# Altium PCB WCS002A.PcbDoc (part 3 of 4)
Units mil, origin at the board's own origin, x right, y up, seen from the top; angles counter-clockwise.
Board outline 2300 x 4058 mil, 4 copper layers (TOP, GND, PWR, BOTTOM), stack 28.8 mil thick; 311 components, 217 nets, 982 pads, 644 vias.
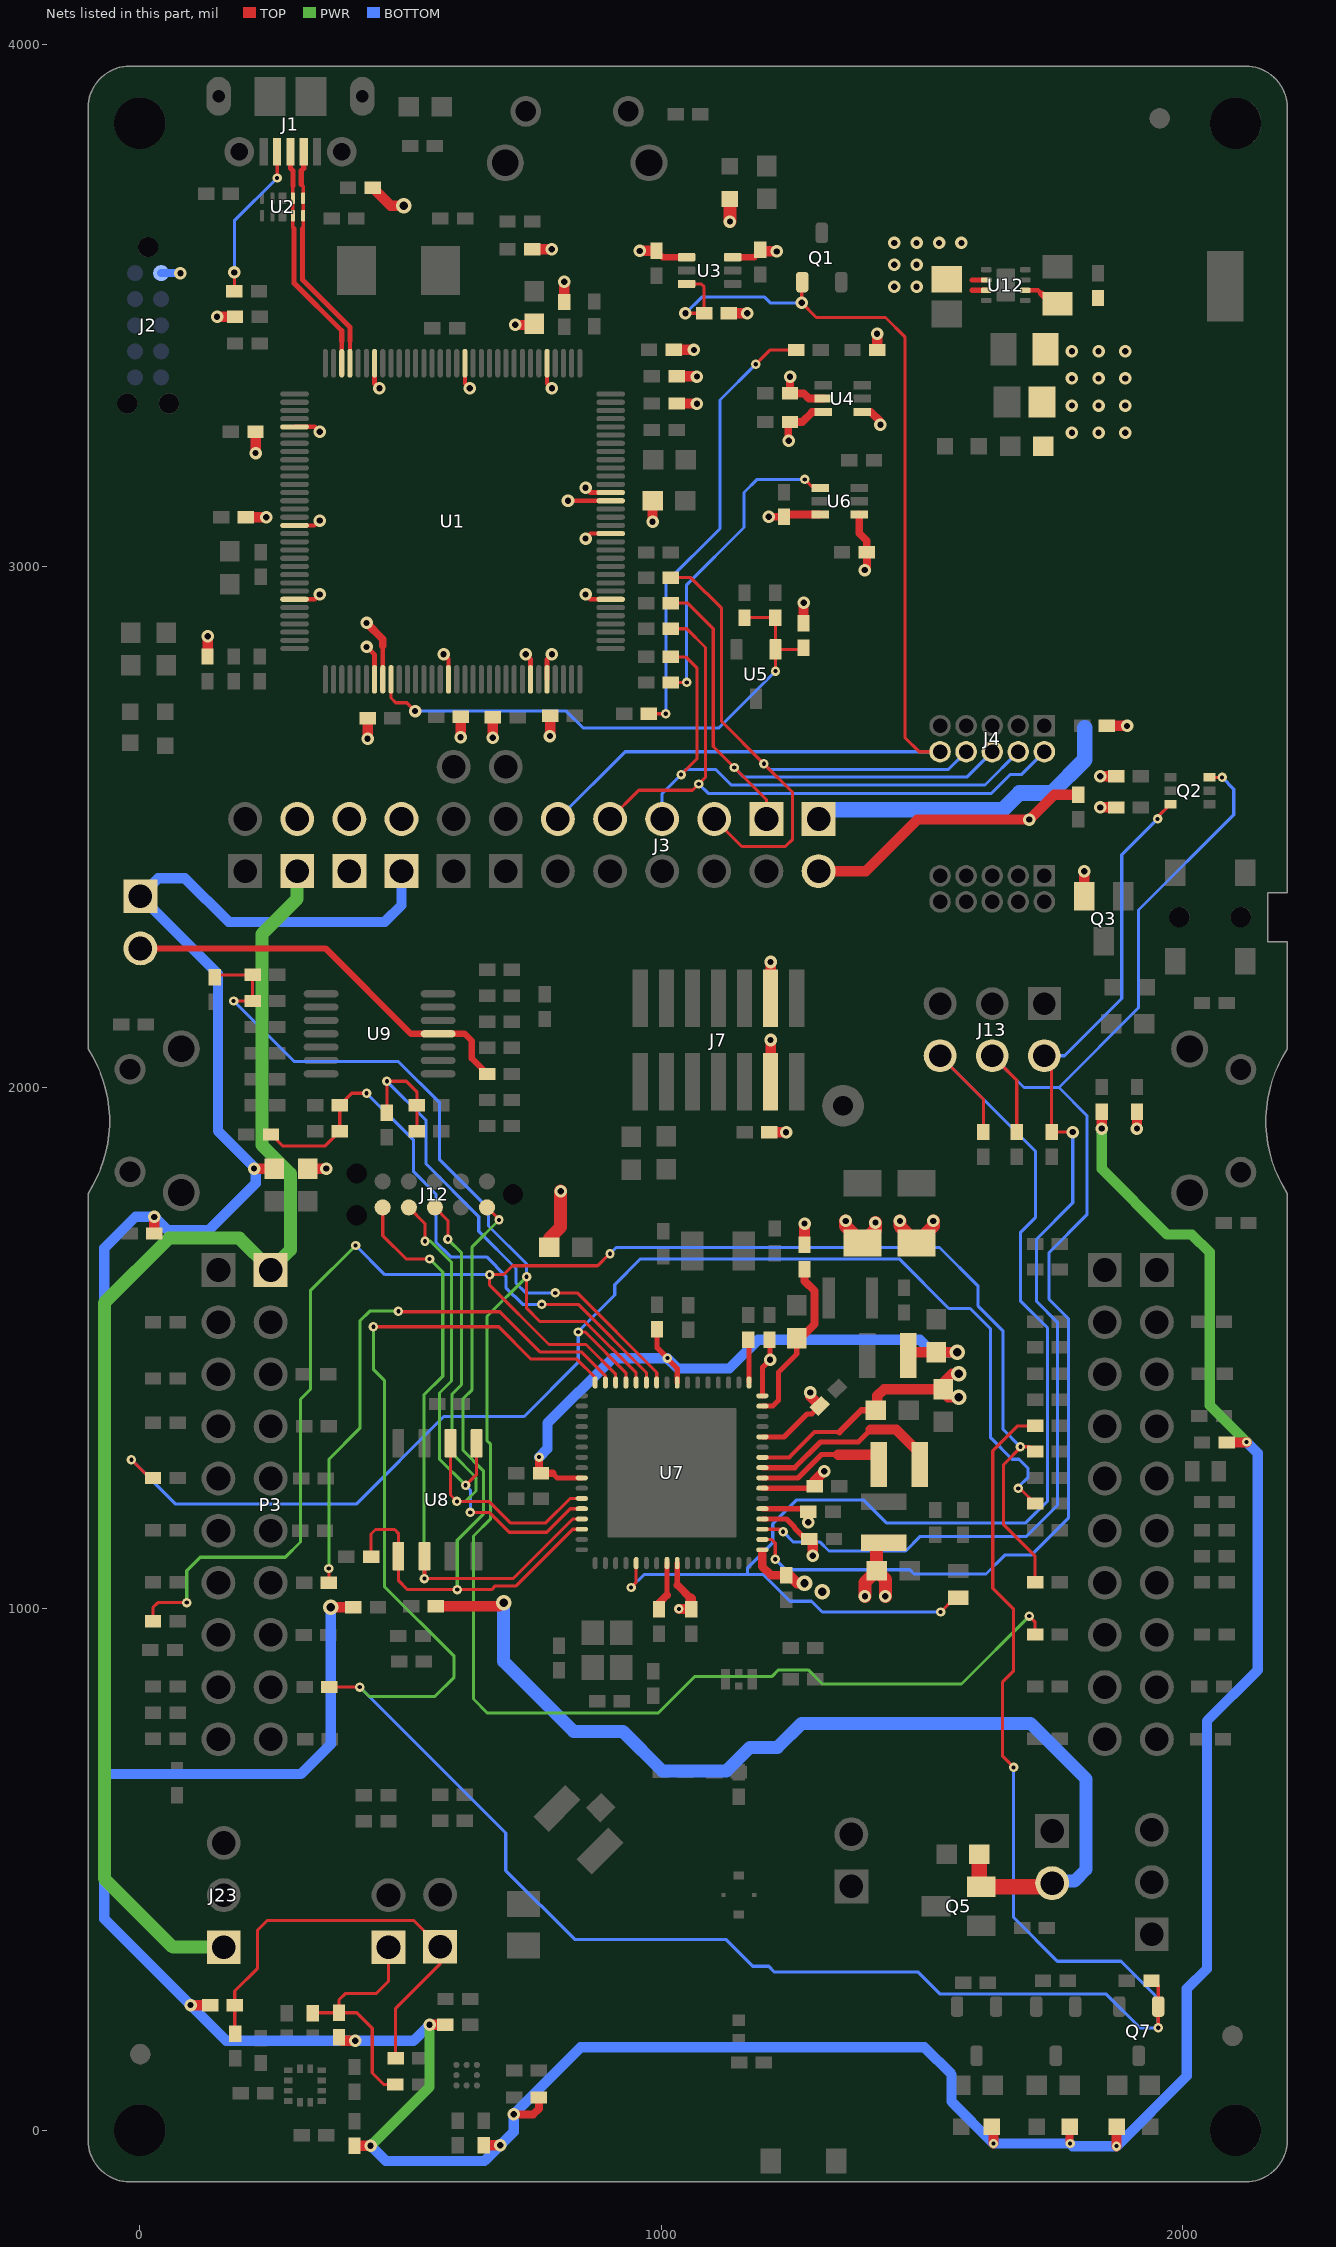
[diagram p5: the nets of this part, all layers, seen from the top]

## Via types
v1: diameter 18, hole 8, TOP to BOTTOM, tented both sides, 344 vias
v2: diameter 24, hole 12, TOP to BOTTOM, tented both sides, 244 vias
v3: diameter 24, hole 12.1, TOP to BOTTOM, 36 vias
v4: diameter 30, hole 16, TOP to BOTTOM, tented both sides, 18 vias
v5: diameter 24, hole 12.1, TOP to BOTTOM, tented top, 2 vias

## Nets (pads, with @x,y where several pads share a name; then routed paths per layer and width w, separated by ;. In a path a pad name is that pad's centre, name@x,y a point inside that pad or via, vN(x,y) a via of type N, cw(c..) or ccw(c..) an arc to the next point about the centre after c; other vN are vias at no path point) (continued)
P58_GPIO_03: C55.1 R108.2 R110.2 U7.58 | length 1051.6
  TOP w6: R108.2@473.79,1951.41 v1(473.79,2011.79) 510.79,2011.79 531.17,1991.41 R110.2@531.17,1965.79 C55.1@531.17,1915.79 ; v1(796.79,1605.79) 838.7,1605.79 991.26,1453.23 U7.58@991.26,1434.02
  BOTTOM w6: v1(473.79,2011.79) 549,1936.57 549,1853 650,1752 650,1724 721.5,1652.5 721.5,1624.5 740.21,1605.79 v1(796.79,1605.79)
P59_GPIO_04: C56.1 R109.2 R111.2 U7.59 | length 1143.9
  TOP w6: R109.2@251.41,1909.79 273.41,1887.79 355.79,1887.79 383.41,1915.41 C56.1@383.41,1915.79 R111.2@383.41,1965.79 406.41,1988.79 v1(434.79,1988.79) ; v1(770.79,1583.79) 840.91,1583.79 971.58,1453.12 U7.59@971.57,1434.02
  BOTTOM w6: v1(434.79,1988.79) 525,1898.57 525,1838 568,1795 568,1703 596,1675 665,1675 702,1638 702,1616 734.21,1583.79 v1(770.79,1583.79)
P60_GPIO_05: C53.1 R77.1 R100.2 R102.2 U7.60 | length 3455.1
  TOP w6: R100.2@143.79,2211.41 148.17,2215.79 C53.1@216.17,2215.79 R102.2@216.17,2165.79 v1(179.79,2165.79) ; v1(741.79,1636.79) 741.79,1575.79 742.15,1576.15 767.5,1550.79 853.79,1550.79 951.87,1452.7 U7.60@951.89,1434.02 ; v1(1705.79,985.79) 1717.17,974.41 R77.1@1717.17,950.79
  PWR w6: v1(741.79,1636.79) 665.79,1560.79 665.79,1322.21 672.79,1315.21 672.79,1172.59 639.79,1139.59 639.79,826.79 666.79,799.79 993.79,799.79 1063.79,869.79 1211.79,869.79 1224.79,882.79 1281.79,882.79 1308.79,855.79 1575.79,855.79 v1(1705.79,985.79)
  BOTTOM w6: v1(179.79,2165.79) 295.79,2049.79 495.79,2049.79 575,1970.57 575,1861 669,1767 669,1754.28 668.79,1754.07 668.79,1734.21 741.79,1661.21 v1(741.79,1636.79)
P61_GPIO_06: R75.1 R98.1 U7.61 | length 2575.1
  TOP w6: v1(-16.21,1285.79) 18.79,1250.79 R75.1@25.17,1250.79 ; v1(840.79,1530.79) 853.99,1530.79 932.21,1452.57 U7.61@932.2,1434.02 ; v1(1684.79,1230.79) 1688.17,1230.79 R98.1@1717.17,1201.79
  BOTTOM w6: v1(-16.21,1285.79) 68.79,1200.79 414.79,1200.79 582.79,1368.79 737.07,1368.79 840.79,1472.5 v1(840.79,1530.79) 840.79,1531.79 910.79,1601.79 910.79,1621.79 960.1,1671.1 1456.4,1671.1 1551.71,1575.79 1592.56,1575.79 1631.79,1536.56 1631.79,1327.79 1672.79,1286.79 1686.07,1286.79 1703.79,1269.07 1703.79,1252.5 1684.79,1233.5 v1(1684.79,1230.79) v1@1685.79,1230.79
P62_GPIO_07: R73.1 R87.1 R94.1 U7.62 | length 3298.6
  TOP w6: R87.1@25.17,975.79 25.17,1002.57 34.39,1011.79 v1(89.79,1011.79) ; v1(901.79,1680.79) 900.79,1680.79 878,1658 714.72,1658 697.5,1640.79 v1(670.79,1640.79) 670.79,1620.79 784.79,1506.79 855.79,1506.79 912.49,1450.08 U7.62@912.52,1434.02 ; R73.1@1717.17,1050.79 1717.17,1100.41 1656.79,1160.79 1656.79,1276.79 1690.79,1310.79 1708.17,1310.79 R94.1@1717.17,1301.79
  PWR w6: v1(89.79,1011.79) 89.79,1072.99 115.59,1098.79 278.79,1098.79 308.1,1128.1 308.1,1401.7 327,1420.6 327,1610 v1(413.79,1696.79)
  BOTTOM w6: v1(413.79,1696.79) 469.79,1640.79 v1(670.79,1640.79) ; v1(901.79,1680.79) 913.79,1692.79 1533.79,1692.79 1607.79,1618.79 1607.79,1580.36 1655.79,1532.36 1655.79,1343.79 v1(1688.79,1310.79)
P63_GPIO_08: R84.2 U7.63 | length 1068.2
  TOP w6: R84.2@362.41,1049.79 v1(362.41,1077.17) ; v1@496.79,1569.79 690.21,1569.79 767.21,1492.79 846.79,1492.79 892.84,1446.74 U7.63@892.83,1434.02
  PWR w6: v1(362.41,1077.17) 362.41,1286.41 422,1346 422,1552 440.79,1570.79 v1(495.79,1570.79)
P64_GPIO_09: Q7.1 R63.1 R90.2 R153.1 U7.64 | length 4846.1
  TOP w6: R90.2@363.41,849.79 v1(421.79,849.79) ; v1(447.79,1540.79) 688.21,1540.79 750.21,1478.79 837.87,1478.79 873.11,1443.54 U7.64@873.11,1434.02 ; v1(1675.79,695.79) 1654.79,716.79 1654.79,859.79 1675.79,880.79 1675.79,999.21 1635.79,1039.21 1635.79,1302.79 1683.79,1350.79 R63.1@1717.17,1350.79 ; R153.1@1938.41,286.79 R153.1@1940.41,286.79 1944.11,286.79 1953.19,277.71 Q7.1@1953.19,237.03 v1(1953.19,196.19)
  PWR w6: v1(421.79,849.79) 439.79,831.79 565.79,831.79 602.79,868.79 602.79,908.79 469,1042.57 469,1438 447.79,1459.21 v1(447.79,1540.79)
  BOTTOM w6: v1(421.79,849.79) 701.79,569.79 701.79,497.79 833.79,365.79 1123.91,365.79 1175.5,314.2 1206.2,314.2 1217.3,303.1 1492.9,303.1 1535.21,260.79 1853.79,260.79 1918.39,196.19 v1(1953.19,196.19) 1953.19,252.41 1881.81,323.79 1759.81,323.79 1675.79,407.81 v1(1675.79,695.79)
PA_SWN: L5.1 U7.41 | length 372.9
  TOP w10: U7.41@1194.02,1270.63 1256.08,1270.63 1305.24,1319.79 1377.78,1319.79 1401.78,1343.79
  TOP w20: 1401.78,1343.79 1450.79,1343.79 1496.16,1298.42 L5.1@1496.16,1276.79
PA_SWP: L5.2 U7.40 | length 261
  TOP w10: U7.40@1194.02,1250.94 1262.38,1250.95 1307.22,1295.79 1339.59,1295.79
  TOP w20: 1339.59,1295.79 1417.42,1295.79 L5.2@1417.42,1276.79
SENS_I2C_SCL: J15.1 R119.2 R133.1 R134.1 | length 466
  TOP w6: R133.1@331.79,224.03 332.79,225.03 R119.2@381.79,225.03 ; J15.1@476.79,350.79 476.79,285.6 452.97,261.79 393.79,261.79 381.79,249.79 R119.2@381.79,225.03 ; R134.1@490.17,87.41 467.79,87.41 445.79,109.41 445.79,195.46 416.22,225.03 R119.2@381.79,225.03
SENS_I2C_SDA: J16.1 R118.2 R130.1 R135.1 | length 845
  TOP w6: R130.1@182.79,185.03 181.89,185.93 R118.2@181.89,239.79 181.89,266.89 225.79,310.79 225.79,383.79 243.79,401.79 525.79,401.79 J16.1@575.79,351.79 575.79,318.79 490.42,233.42 R135.1@490.42,137.62
SFL_CLK: J12.8 U7.11 U8.6 | length 1019
  TOP w6: J12.8@565.79,1769.79 590.79,1744.79 v1(590.79,1708.79) ; U8.6@595.79,1307.28 595.79,1218.19 v1(608.03,1205.94) 669.46,1205.94 710.61,1164.79 778.79,1164.79 825.58,1211.58 U7.11@847.56,1211.57
  PWR w6: v1(590.79,1708.79) 616.79,1682.79 616.79,1429.79 598.79,1411.79 598.79,1297.79 644.79,1251.79 644.79,1225.79 624.94,1205.94 v1(608.03,1205.94)
SFL_CS: J12.10 R41.2 U7.14 U8.1 | length 1407.8
  TOP w6: R41.2@443.41,1099.79 443.41,1143.41 451.9,1151.9 488.7,1151.9 495.79,1144.81 U8.1@495.79,1100.74 495.79,1054.41 513.41,1036.79 v1(608.79,1036.79) 674.59,1036.79 681.59,1043.79 721.59,1043.79 830.32,1152.52 U7.14@847.56,1152.52 ; J12.10@665.79,1769.79 688.79,1746.79 v1(688.79,1745.79)
  PWR w6: v1(608.79,1036.79) 608.79,1131.5 658.79,1181.5 658.79,1264.79 619.79,1303.79 619.79,1402.79 637.2,1420.2 637.2,1694.2 v1(688.79,1745.79)
SFL_DIN: J12.6 U7.13 U8.2 | length 1212
  TOP w6: J12.6@465.79,1769.79 465.79,1715.79 510.79,1670.79 v1(555.79,1670.79) ; v1(545.79,1057.79) 715.79,1057.79 830.21,1172.21 U7.13@847.56,1172.2
  TOP w8: v1(545.79,1057.79) U8.2@545.79,1100.74 U8.2@545.79,1119.72
  PWR w6: v1@544.79,1057.79 544.79,1409.99 580.79,1445.99 580.79,1645.79 v1(555.79,1670.79)
SFL_DOUT: J12.7 U7.12 U8.5 | length 991.2
  TOP w6: J12.7@515.79,1769.79 546.79,1738.79 v1(546.79,1704.79) ; v1(624.79,1236.79) 645.79,1257.79 U8.5@645.79,1311.85 ; v1(633.79,1184.79) 670.31,1184.79 708.31,1146.79 780.59,1146.79 825.69,1191.89 U7.12@847.56,1191.89
  PWR w6: v1(546.79,1704.79) 557.54,1704.79 597.79,1664.54 597.79,1436.79 574.79,1413.79 574.79,1286.79 v1(624.79,1236.79)
  BOTTOM w6: v1(624.79,1236.79) 633.79,1227.79 v1(633.79,1184.79)
SOP0: J13.2 Q2.3 R49.1 U7.35 | length 2179.2
  TOP w6: U7.35@1194.02,1152.52 1229.06,1152.52 v1(1233.79,1147.79) ; J13.2@1734.79,2060.79 1748.79,2046.79 R49.1@1748.79,1914.41 v2(1789.41,1914.41) ; v1(1952.09,2514.99) 1952.09,2518.8 Q2.3@1976.69,2543.4
  BOTTOM w6: v1(1233.79,1147.79) 1253.79,1127.79 1304.79,1127.79 1321.79,1110.79 1468.79,1110.79 1496.79,1138.79 1700.49,1138.79 1759.79,1198.09 1759.79,1549.79 1719.79,1589.79 1719.79,1708.79 1789.41,1778.41 v2(1789.41,1914.41) ; J13.2@1734.79,2060.79 1773.49,2060.79 1883.3,2170.6 1883.3,2446.2 v1(1952.09,2514.99)
SOP1: J13.4 Q2.6 R50.1 U7.34 | length 2656.6
  TOP w6: U7.34@1194.02,1132.83 1211.79,1132.84 1218.79,1125.84 v1(1218.79,1095.01) ; J13.4@1634.79,2060.79 1681.79,2013.79 R50.1@1681.79,1914.41 ; Q2.6@2051.49,2594.58 v1(2075.81,2594.58)
  BOTTOM w6: v1(1218.79,1095.01) 1239.01,1074.79 1476.79,1074.79 1484.79,1066.79 1622.79,1066.79 1658.79,1102.79 1709.79,1102.79 1780.79,1173.79 1780.79,1556.79 1743.79,1593.79 1743.79,1682.79 1816.4,1755.4 1816.4,1946.17 1762.79,1999.79 ; J13.4@1634.79,2060.79 1695.79,1999.79 1762.79,1999.79 ; v1(2075.81,2594.58) 2098.2,2572.19 2098.2,2522.9 1915.5,2340.2 1915.5,2152.5 1762.79,1999.79
SOP2: D4.2 J13.6 R51.1 U7.21 | length 2572.8
  TOP w6: v1(942.12,1040.79) 951.89,1050.56 U7.21@951.89,1087.56 ; J13.6@1534.79,2060.79 1617.79,1977.79 R51.1@1617.79,1914.41 ; v1(1535.79,993.79) 1563.2,1021.2 D4.2@1569.79,1021.2
  BOTTOM w6: v1(942.12,1040.79) 967.12,1065.79 1165.79,1065.79 ; J13.6@1534.79,2060.79 1717.6,1877.97 1717.6,1750.3 1688.79,1721.49 1688.79,1590.79 1740.79,1538.79 1740.79,1206.29 1699.29,1164.79 1431.79,1164.79 1387.79,1208.79 1259.79,1208.79 1213.79,1162.79 1213.79,1126.79 1165.79,1078.79 1165.79,1065.79 ; v1(1535.79,993.79) 1309.01,993.79 1288.3,1014.5 1247.07,1014.5 1195.79,1065.79 1165.79,1065.79
VBAT_CC: C29.1 C30.1 C31.1 C63.1 C64.1 J7.3 J7.4 J9.2 J19.1 Q5.2 R30.2 R36.2 R39.2 R43.2 R56.1 R150.2 U7.37 U7.39 U7.44 | length 3019.9
  TOP w10: U7.37@1194.02,1191.89 1276.06,1191.89 C29.1@1282.17,1185.79 ; U7.39@1194.02,1231.26 1281.97,1231.26 1292.2,1241.5 1294.17,1241.5 C30.1@1303.5,1241.5 ; U7.44@1194.02,1329.68 1235.23,1329.69 1279.33,1373.79 1288.79,1373.79 C31.1@1304.08,1389.08 C31.1@1307.15,1392.15
  TOP w12: v2(1281.79,1165.79) 1281.79,1185.41 C29.1@1282.17,1185.79
  TOP w19.9: R56.1@321.79,1844.28 v2(357.49,1844.28) ; R39.2@567.79,1004.79 688.79,1004.79 v4@696.79,1012.79 ; R30.2@1207.03,1914.17 v2(1239.49,1914.17)
  TOP w20: v4@696.79,1012.79 v4(697.79,1011.79) ; J7.4@1209.79,2015.98 v2@1209.79,2090.42 ; J7.3@1209.79,2165.59 J7.3@1209.79,2170.91 v2@1209.79,2240.03 ; v2(1285.79,1414.79) 1285.79,1407.38 C31.1@1304.08,1389.08 ; C30.1@1294.17,1234.79 1294.17,1241.5 1294.17,1245.17 v2(1312.79,1263.79)
  TOP w22: R43.2@1274.79,1698.41 v2(1274.79,1738.79)
  TOP w25: R36.2@785.29,1693.79 785.29,1710.29 807.17,1732.17 v2(807.17,1800.97) ; v2(1353.79,1743.79) 1353.79,1733.7 C64.1@1385.79,1701.7 1410.79,1726.7 v2(1410.79,1740.79) ; v2(1457.79,1743.79) 1457.79,1733.7 C63.1@1489.79,1701.7 1521.79,1733.7 v2(1521.79,1743.79)
  TOP w30: R150.2@1610.28,528.79 1610.28,470.29 Q5.2@1613.79,466.79 1742.79,466.79 J9.2@1749.79,473.79
  BOTTOM w25: v4(697.79,1011.79) 697.79,898.79 831.79,764.79 926.38,764.79 1002.38,688.79 1124.79,688.79 1169.79,733.79 1222.79,733.79 1269.29,780.29 1708.29,780.29 1814.79,673.79 1814.79,499.79 1792.79,477.79 J9.2@1735.79,477.79
  other v2: 1209.79,2090.91 1209.79,2240.51
VBUS_USB1: C62.1 J20.2 L1.2 R13.1 R15.1 U12.2 U12.3 | length 201.2
  TOP w10: 1596.3,3528.7 1596.54,3528.94 U12.3@1623.39,3528.94 ; 1596.3,3548.7 1596.37,3548.63 U12.2@1623.39,3548.63
  TOP w20: R15.1@129.79,2826.41 v2@129.79,2865.03 ; v2(148,3478) R13.1@182.38,3478 ; L1.2@446.41,3725.79 481.41,3690.79 v4(505.79,3690.79)
  other v2: 130.17,2865.41 1446.79,3535.79 1489.79,3535.79 1446.79,3577.79 1489.79,3577.79 1446.79,3619.79 1489.79,3619.79 1532.79,3619.79 1575.79,3619.79
VCC_5V: J20.1 J23.1 P3.1 | length 2613.9
  PWR w25: J23.1@160.79,350.79 63.19,350.79 -68.21,482.19 -68.21,1586.79 55.79,1710.79 190.79,1710.79 P3.1@249.96,1651.62 ; P3.1@249.96,1649.79 288.79,1688.62 288.79,1834.79 234,1889.57 234,2294 301.79,2361.79 J20.1@301.79,2414.79
VCC_BRD: D8.1 D9.2 D10.2 J14.1 J17.1 J18.2 Q3.2 R32.1 R38.2 R47.1 R57.1 R116.2 R117.2 R118.1 R119.1 R120.2 R121.2 R136.1 R137.2 R138.1 R139.1 R140.2 | length 9757.3
  TOP w15: v2(716.96,30.24) 754.61,30.24 765.41,41.03 R120.2@765.41,62.62 ; D9.2@1783.28,6.79 1783.28,-24.71 v1(1784.29,-25.71)
  TOP w19.9: R138.1@27.41,1719.79 v2(27.41,1751.6) ; v2(219.09,1844.28) R57.1@257.79,1844.28 ; v4(366.1,1002.79) R38.2@409.46,1002.79 ; J18.2@1301.79,2414.79 1391.99,2414.79 1491,2513.8 v2(1706,2513.8) ; D8.1@1634.31,6.79 1637.29,3.81 v1(1637.29,-25.71) ; v2(1844.8,1921.09) R47.1@1844.8,1953.54 ; v1(1873.29,-30.71) D10.2@1873.31,6.79 ; v2(1912.41,1921.09) R139.1@1912.41,1953.54 ; R136.1@2084.41,1318.79 2121.79,1318.79 v1(2122.79,1319.79)
  TOP w20: v2(97.17,239.79) R118.1@134.65,239.79 ; R119.1@381.79,177.79 387.79,171.79 412.61,171.79 v2(412.89,171.51) ; R117.2@411.79,-30.21 v2(442.41,-30.21) ; v2(555.52,202.14) R121.2@586.09,202.14 ; R116.2@659.31,-28.91 v2@690.94,-28.91 ; v2(1706,2513.8) 1753.61,2561.41 R32.1@1799.91,2561.41 ; Q3.2@1811.59,2366.82 v2(1811.59,2414.38) ; v2(1842.09,2536.99) R140.2@1872.47,2536.99 ; v2(1842.09,2596.99) R137.2@1872.47,2596.99
  PWR w19.9: v2(1844.8,1921.09) 1844.8,1843.77 1970.79,1717.79 2017.79,1717.79 2052,1683.57 2052,1390.57 v1(2122.79,1319.79)
  PWR w20: v2(442.41,-30.21) 555.52,82.9 v2(555.52,202.14)
  BOTTOM w19.9: v4@366.1,1002.1 366.1,740.1 309,683 -68.21,683 ; J17.1@501.79,2414.79 501.79,2349.19 469.9,2317.3 170,2317.3 86.5,2400.8 35.3,2400.8 J14.1@1,2366.5 149.79,2217.71 149.79,1916.58 222.09,1844.28 222.09,1816.09 131.98,1725.98 53.03,1725.98 v2(27.41,1751.6) -8.4,1751.6 -68.21,1691.79 -68.21,683 ; v2(555.52,202.14) 524.89,171.51 v2(412.89,171.51) 165.44,171.51 v2(97.17,239.79) -68.21,405.17 -68.21,683 ; v2(716.96,30.24) 845.51,158.79 1504.79,158.79 1556.79,106.79 1556.79,54.79 v1(1637.29,-25.71) v1(1784.29,-25.71) 1789.29,-30.71 v1(1873.29,-30.71) 2007.79,103.79 2007.79,270.79 2046.79,309.79 2046.79,784.79 2144.43,882.43 2144.43,1298.14 v1(2122.79,1319.79)
  BOTTOM w20: v2(442.41,-30.21) 471.41,-59.21 661.01,-59.21 v2(691.31,-28.91) 716.96,-3.26 v2(716.96,30.24)
VCC_LDO_3V3: C4.1 C7.1 C8.1 C9.1 C10.1 C11.1 C12.1 C14.1 C15.1 C16.1 C24.1 C60.1 C61.1 J2.1 J17.2 J19.2 L8.2 R7.1 R9.1 R10.1 R20.1 R25.2 R28.1 R29.1 R145.1 R146.2 U1.7 U1.8 U1.16 U1.26 U1.28 U1.39 U1.47 U1.51 U1.52 U1.69 U1.79 U1.90 U1.101 U1.113 U1.122 U3.6 U4.6 U6.6 U12.6 | length 1880.9
  TOP w7.5: U1.113@296.64,3077.91 335.42,3077.91 v2(344.79,3087.28) ; v2(582.54,2830.79) 591.91,2821.42 U1.16@591.91,2782.64 ; U1.79@623.41,3388.94 623.41,3350.16 v2(632.78,3340.79) ; U1.69@780.89,3388.94 780.89,3350.16 v2(790.26,3340.79) ; v2(854.79,3052.8) 864.16,3062.17 U1.47@902.94,3062.17
  TOP w8: U12.6@1698.19,3528.94 1722.63,3528.94 1728.79,3522.79
  TOP w9: U1.122@296.64,2936.18 335.42,2936.18 v2(344.79,2945.55) ; U1.101@296.64,3266.89 335.42,3266.89 v2(344.79,3257.52) ; v2(434.79,2844.79) 450.18,2829.39 U1.7@450.18,2782.64 ; U1.90@450.18,3388.94 450.18,3350.16 v2(459.55,3340.79) ; U1.8@465.93,2782.64 465.93,2847.65 ; v2(740.02,2830.79) 749.39,2821.42 U1.26@749.39,2782.64 ; U1.28@780.89,2782.64 780.89,2821.42 v2(790.26,2830.79) ; v2(821.16,3125.16) U1.51@902.94,3125.16 ; v2(854.79,2945.55) 864.16,2936.18 U1.39@902.94,2936.18 ; v2(854.79,3150.28) 864.16,3140.91 U1.52@902.94,3140.91
  TOP w12: U3.6@1137.08,3592.38 1178.76,3592.38 C4.1@1189.79,3603.41 ; 1728.79,3522.79 1748.22,3503.35 L8.2@1759.79,3503.35
  TOP w15: v2(434.79,2890.79) 465.93,2859.65 465.93,2847.65 ; v2(1206.39,3094.57) C24.1@1235.39,3094.57 1239.72,3098.91 C24.1@1244.39,3098.91 ; v2@1243.68,3240.91 1243.68,3272.87 C14.1@1247.01,3276.2 1270.39,3276.2 1289.39,3295.2 1310.57,3295.2 U4.6@1310.98,3295.61 ; C24.1@1245.7,3098.61 U6.6@1304.98,3098.61
  TOP w20: C8.1@203.41,3093.79 v2@242.03,3093.79 ; v2@222.17,3217.17 C9.1@222.17,3255.79 ; v2@437.17,2669.17 C15.1@437.17,2707.79 ; v2@615.41,2672.17 C12.1@615.41,2710.79 ; v2@677.17,2671.17 C16.1@677.17,2709.79 ; v2@720.17,3462.28 C10.1@758.79,3462.28 ; R20.1@752.41,3607.79 v2(789.79,3607.79) ; v2@786.79,2674.17 C7.1@786.79,2712.79 ; R28.1@813.79,3506.41 v2@813.79,3545.03 ; v2(983.29,3085.1) C11.1@983.29,3124.79 ; R7.1@1023.79,3414.79 v2@1062.41,3414.79 ; R10.1@1029.41,3311.79 v2@1068.03,3311.79 ; R9.1@1029.41,3363.79 v2@1068.03,3363.79 ; C4.1@1189.79,3603.41 v2(1221.6,3603.41) ; R25.2@1272.79,2890.41 v2@1272.79,2929.03 ; R29.1@1854.41,2693.79 v2@1893.03,2693.79
  BOTTOM w15: J2.1@40.79,3561.79 v2(77.79,3561.79)
  other v2: 436.79,2668.79 676.79,2670.79 615.03,2671.79 786.41,2673.79 1893.41,2693.41 1273.17,2929.41 242.41,3093.41 221.79,3216.79 1244.39,3240.2 1787.79,3255.79 1838.79,3255.79 1889.79,3255.79 1787.79,3307.79 1838.79,3307.79 1889.79,3307.79 1068.41,3311.41 1787.79,3359.79 1838.79,3359.79 1889.79,3359.79 1068.41,3363.41 1787.79,3411.79 1838.79,3411.79 1889.79,3411.79 1062.79,3414.41 719.79,3462.66 814.17,3545.41
VCC_OPAMP: C52.1 J14.2 U9.4 | length 784.6
  TOP w12: J14.2@1,2266.5 356.07,2266.5 519.79,2102.79 U9.4@571.99,2102.79 622.79,2102.79 636.42,2089.16 636.42,2055.54 C52.1@666.17,2025.79
VCC_SENSE: C5.1 C17.1 C25.1 D3.2 J18.1 R17.2 R26.1 U3.1 U4.1 U4.5 U6.1 | length 1086.7
  TOP w12: C5.1@990.79,3604.41 1002.82,3592.38 U3.1@1048.5,3592.38
  TOP w15: v2(1247.01,3363.01) C17.1@1247.01,3331.2 1273.39,3331.2 1283.29,3321.3 1310.88,3321.3 U4.5@1310.98,3321.2 ; U6.1@1379.79,3098.61 1379.79,3062.77 1394.01,3048.55 C25.1@1394.01,3026.2 ; U4.1@1385.79,3295.61 1401.98,3295.61 1420.39,3277.2 v2(1420.39,3271.2) ; v2(1390.39,2992.2) 1394.68,2996.49 C25.1@1394.68,3027.2
  TOP w19.9: R26.1@1414.01,3414.2 v2(1414.01,3445.3)
  TOP w20: v2(958.98,3604.41) C5.1@990.79,3604.41 ; R17.2@1129.41,3484.79 v2(1165.16,3484.79)
  TOP w25: v2(1131.79,3660.79) D3.2@1131.79,3703.99
  BOTTOM w30: J18.1@1301.79,2514.79 1319.3,2532.3 1654.7,2532.3 1687.1,2564.7 1748.7,2564.7 1812.4,2628.4 1812.4,2689.6
VDD_ANA: C35.1 C36.1 C37.1 C38.1 L4.1 U7.25 U7.36 U7.48 | length 562.1
  TOP w10: U7.25@1030.63,1087.56 1030.63,1045.79 1031.45,1044.97 ; U7.36@1194.02,1172.2 1240.48,1172.2 1255.79,1156.9 1255.79,1154.79 1271.17,1139.41 1278.54,1139.41 C37.1@1284.17,1133.79 ; U7.48@1194.02,1408.42 1194.02,1463.02 v2(1208.79,1477.79) 1208.79,1515.17 C36.1@1207.79,1516.17
  TOP w15: 1031.45,1044.97 1056.79,1019.63
  TOP w19.9: v1@1034.41,999.41 C38.1@1057.79,999.41 ; C38.1@1056.79,1001.08 1056.79,1019.63
  TOP w20: C37.1@1284.17,1133.79 1290.79,1127.17 v2(1290.79,1101.79)
  TOP w25: v2(1390.79,1023.79) 1390.79,1050.79 1412.79,1072.79 C35.1@1413.29,1072.79 ; C35.1@1407.29,1078.79 C35.1@1413.29,1072.79 ; C35.1@1413.29,1077.79 1413.29,1126.42 L4.1@1426.79,1126.42 ; v2(1429.79,1023.79) 1429.79,1056.29 C35.1@1413.29,1072.79
  other v1: 1033.79,999.79
VDD_DIG_CC: C42.1 C43.1 C44.1 L6.1 U7.9 U7.56 | length 1279
  TOP w10: 791.63,1259.79 800.47,1250.95 U7.9@847.56,1250.94 ; C44.1@991.79,1536.17 991.79,1500.79 v1(1011.79,1480.79) 1011.79,1479.42 1030.63,1460.58 U7.56@1030.63,1434.02
  TOP w15: v1(765.79,1290.79) 765.79,1264.17 769.79,1260.17 C43.1@769.41,1259.79 791.63,1259.79
  TOP w19.9: L6.1@1474.16,1485.79 1480.66,1492.29 C42.1@1527.79,1492.29 v4(1567.6,1492.29)
  BOTTOM w19.9: v1(765.79,1290.79) 781.79,1306.79 781.79,1355.79 906.79,1480.79 v1(1011.79,1480.79) 1031.74,1460.84 1130.84,1460.84 1185.79,1515.79 1495.79,1515.79 1519.28,1492.29 v4(1567.6,1492.29)
VDD_FL: C45.1 R43.1 U7.47 | length 327.9
  TOP w10: U7.47@1194.02,1388.74 1213.74,1388.74 1224.79,1399.79 1224.79,1453.79 1259.79,1488.79 C45.1@1259.79,1519.29
  TOP w15: C45.1@1259.79,1519.29 1267.29,1519.29 1294.14,1546.14 1294.14,1609.44 1274.79,1628.79 R43.1@1274.79,1651.17
VDD_PA: C39.1 C40.1 C41.1 U7.33 U7.42 | length 641.4
  TOP w8: 1193.6,1096.1 1194.02,1096.52 U7.33@1194.02,1113.15 ; U7.42@1194.02,1290.31 1245.36,1290.31 1293.83,1338.79 1341.79,1338.79
  TOP w12: 1341.79,1338.79 1383.79,1380.79 C39.1@1411.29,1380.79
  TOP w16: 1193.6,1105.1 1193.6,1080.97 1210.17,1064.41 C41.1@1239.79,1064.41
  TOP w19.9: C40.1@1539.79,1416.28 1550.35,1405.72 1550.43,1405.79 v4(1570.79,1405.79) ; C40.1@1539.79,1421.28 1539.79,1432.79 1557.79,1450.79 v4(1570.79,1450.79)
  TOP w20: C41.1@1239.79,1064.41 1245.56,1064.41 1261.18,1048.79 v4(1274.79,1048.79) ; C39.1@1414.29,1373.79 1414.29,1408.29 1427.28,1421.28 C40.1@1539.79,1421.28
  other v4: 1308.79,1032.79
VDD_PLL: C47.1 U7.24 | length 88.8
  TOP w10: 1010.79,1025.79 1010.95,1025.95 U7.24@1010.94,1087.56
  TOP w15: C47.1@995.78,1005.07 995.78,1010.78 1010.79,1025.79
VDD_RAM: C46.1 U7.49 | length 82.8
  TOP w10: C46.1@1166.79,1516.17 1168.46,1514.49 U7.49@1168.46,1434.02
VREFA: C21.1 C22.1 R25.1 U1.9 U5.1 | length 1057
  TOP w6: U1.9@481.68,2782.64 481.68,2746.9 490.79,2737.79 511.79,2737.79 v2(527.79,2721.79) ; C21.1@1161.79,2901.17 C22.1@1218.79,2901.17 1219.19,2900.76 U5.1@1219.19,2840.03 ; v1(1219.19,2798.39) U5.1@1219.19,2840.03 ; R25.1@1272.79,2843.17 1269.65,2840.03 U5.1@1219.19,2840.03
  BOTTOM w6: v2(527.79,2721.79) 817.79,2721.79 850.17,2689.41 1110.21,2689.41 v1(1219.19,2798.39)
XDS_JTAG_TCK: J3.5 J4.4 R3.1 | length 1066
  TOP w6: R3.1@1018.41,2825.79 1046.79,2825.79 1068.79,2803.79 1068.79,2630.79 v1(1038,2600)
  BOTTOM w6: J3.5@1001.79,2514.79 1001.79,2563.79 v1(1038,2600) 1048,2610 1104,2610 1134,2580 1621,2580 J4.4@1684.79,2643.79
XDS_JTAG_TDI: J3.3 J4.8 R6.1 | length 1205.4
  TOP w6: R6.1@1018.41,2977.79 1056.79,2977.79 1115.79,2918.79 1115.79,2701.79 v1(1196.79,2620.79) 1252,2565.57 1252,2476 1238,2462 1154.57,2462 J3.3@1101.79,2514.79
  BOTTOM w6: v1(1196.79,2620.79) 1207.57,2610 1551,2610 J4.8@1584.79,2643.79
XDS_JTAG_TDO: J3.1 J4.6 R5.1 | length 1031.6
  TOP w6: R5.1@1018.41,2928.79 1050.79,2928.79 1099.79,2879.79 1099.79,2653.79 v1(1140,2613.57) 1201.79,2551.79 J3.1@1201.79,2514.79
  BOTTOM w6: v1(1140,2613.57) 1158.57,2595 1586,2595 J4.6@1634.79,2643.79
XDS_JTAG_TMS: J3.7 J4.2 R4.1 | length 1249.7
  TOP w6: J3.7@901.79,2514.79 957,2570 1060,2570 v1(1072,2582) 1084.79,2594.79 1084.79,2843.79 1048.79,2879.79 R4.1@1018.41,2879.79
  BOTTOM w6: v1(1072,2582) 1090,2564 1633.4,2564 1669.8,2600.4 1691.4,2600.4 J4.2@1734.79,2643.79
XDS_NRESET: J3.9 J4.10 Q1.1 R17.1 U3.3 | length 2260
  TOP w6: v2(1046.42,3484.79) R17.1@1082.17,3484.79 1082.17,3535.41 1076.38,3541.2 U3.3@1048.5,3541.2 ; Q1.1@1269.39,3543.39 v2(1269.39,3504.86) 1297.46,3476.79 1430.21,3476.79 1467.39,3439.61 1467.39,2671.01 1494.61,2643.79 J4.10@1534.79,2643.79
  BOTTOM w6: J3.9@801.79,2514.79 930.79,2643.79 J4.10@1534.79,2643.79 ; v2(1046.42,3484.79) 1077.42,3515.79 1198.21,3515.79 1209.14,3504.86 v2(1269.39,3504.86)
XDS_UART_RX: R1.1 R27.2 | length 862.8
  TOP w6: R1.1@976.41,2716.79 v1(1008.79,2716.79) ; v1(1181.39,3387.2) 1208.39,3414.2 R27.2@1258.76,3414.2
  BOTTOM w6: v1(1008.79,2716.79) 1008.79,2967.79 1112.79,3071.79 1112.79,3318.6 v1(1181.39,3387.2)
XDS_UART_TX: R2.1 U6.4 | length 603.6
  TOP w6: R2.1@1018.41,2776.79 v1(1048.79,2776.79) ; v1(1275.39,3166.2) 1291.8,3149.79 U6.4@1304.98,3149.79
  BOTTOM w6: v1(1048.79,2776.79) 1048.79,2963.79 1158.79,3073.79 1158.79,3141.1 1183.89,3166.2 v1(1275.39,3166.2)
XDSET_DM: J1.2 U1.93 U2.1 U2.10 | length 447.6
  TOP w7: 309.58,3732.05 313.16,3728.47 U2.1@313.16,3705.52 U2.10@313.16,3672.06 313.16,3648.16 311.79,3646.79
  TOP w8: U1.93@402.94,3388.94 402.94,3431.64 403.06,3431.76
  TOP w10: 309.58,3732.05 309.58,3758.27 314.38,3763.06 J1.2@314.38,3794.64 ; 311.79,3646.79 311.79,3549.21 403.06,3457.94 403.06,3431.76
XDSET_DP: J1.3 U1.94 U2.2 U2.9 | length 446.6
  TOP w7: 293.47,3729.42 U2.2@293.47,3705.52 U2.9@293.47,3672.06 293.47,3649.1 295.79,3646.79
  TOP w8: 387.06,3431.51 387.19,3431.39 U1.94@387.19,3388.94
  TOP w10: J1.3@288.79,3794.64 288.79,3763.06 293.58,3758.27 293.58,3729.53 293.47,3729.42 ; 295.79,3646.79 295.79,3542.59 387.06,3451.31 387.06,3431.51
XDSET_ID: J1.4 R12.1 | length 299.8
  TOP w6: R12.1@181.17,3526.79 v2(181.17,3563.17)
  TOP w7: v1(263.2,3744.38) J1.4@263.2,3792.64
  BOTTOM w6: v2(181.17,3563.17) 181.17,3662.35 v1(263.2,3744.38)
pads on no net: FID1.1 FID2.1 FID3.1 FID4.1 FID5.1 FID6.1 J2.7 J2.9 J2.MH1 J2.MH2 J2.MH3 J7.7 J7.8 J12.3 J12.4 J12.5 J12.MH1 J12.MH2 J12.MH3 LBL1.0 SW1.MH1 SW1.MH2 SW2.MH1 SW2.MH2 SW3.MH1 SW3.MH2 SW4.MH1 SW4.MH2 U1.2 U1.5 U1.6 U1.11 U1.12 U1.13 U1.14 U1.15 U1.18 U1.19 U1.20 U1.21 U1.22 U1.23 U1.24 U1.25 U1.27 U1.29 U1.30 U1.31 U1.32 U1.41 U1.42 U1.43 U1.44 U1.45 U1.46 U1.49 U1.50 U1.53 U1.54 U1.56 U1.57 U1.65 U1.67 U1.71 U1.72 U1.73 U1.74 U1.75 U1.76 U1.77 U1.78 U1.81 U1.82 U1.83 U1.84 U1.85 U1.86 U1.91 U1.92 U1.102 U1.103 U1.104 U1.105 U1.106 U1.107 U1.108 U1.109 U1.110 U1.111 U1.112 U1.116 U1.117 U1.118 U1.119 U1.120 U1.121 U1.123 U1.124 U1.125 U1.126 U1.127 U1.128 U2.4 U2.5 U2.6 U2.7 U5.3 U7.26 U7.27 U7.28 U10.C2 U11.4 U11.6 U11.10
copper on no net:
  other v1: 749.79,510.79 722.79,541.79

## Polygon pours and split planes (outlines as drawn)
VDD_PA on TOP "Bottom Layer-VDD_PA" (solid, remove dead copper, pour order 42): 1220.79,1084.79 1220.79,1033.79 1272.8,1033.79 1289.8,1016.79 1324.79,1016.79 1332.79,1024.79 1332.79,1048.79 1332.79,1050.79 1311.79,1071.79 1290.79,1071.79 1277.79,1084.79 1221.79,1084.79
GND on TOP "Top Layer-GND" (solid, remove dead copper, pour order 46): -95.8,3955.79 2155.01,3955.79 2203.1,3907.7 2203.1,-61.8 2168,-96.9 -67.4,-96.9 -95.8,-68.5
NetC3_1 on TOP "Bottom Layer-NetC2_1" (solid, remove dead copper, pour order 43): 354.79,2742.79 364.79,2752.79 364.79,2806.79 357.79,2813.79 257.79,2813.79 250.79,2806.79 246.79,2802.79 108.79,2802.79 96.79,2790.79 96.79,2755.79 109.79,2742.78
VCC_LDO_3V3 on TOP "Bottom Layer-VCC_LDO_3V3" (solid, remove dead copper, pour order 45): 1725.79,3523.79 1725.79,3480.79 1702.79,3457.79 1702.79,3296.79 1708.79,3290.79 1708.79,3197.79 1722.79,3183.79 1891.79,3183.79 1912.79,3204.79 1912.79,3499.79 1881.79,3530.79 1732.79,3530.79
VBUS_USB1 on TOP "Bottom Layer-VBUS_USB1" (solid, remove dead copper, pour order 44): 1628.79,3518.79 1635.79,3525.79 1635.79,3553.79 1632.79,3556.79 1607.79,3556.79 1604.79,3559.79 1604.79,3620.79 1578.79,3646.79 1436.79,3646.79 1425.79,3635.79 1425.79,3528.79 1435.78,3518.79
GND on BOTTOM "Top Layer-GND" (solid, remove dead copper, pour order 57): -81.81,3954.79 2126.4,3954.79 2183.19,3898 2183.19,-9.43 2113.19,-79.43 43.19,-79.43 -81.81,45.57
VBUS_USB1 on BOTTOM "Bottom Layer-VBUS_USB1" (solid, remove dead copper, pour order 55): 265.72,2459.86 353.86,2459.86 361,2467 361,2881.57 307.2,2935.38 304.79,2937.79 296,2946.57 296,3001 296,3325 461.79,3490.79 879.79,3490.79 912.79,3523.79 912.79,3621.79 979.87,3688.87 1367.71,3688.87 1406.79,3649.79 1406.79,3527.79 1431.6,3502.98 1578.98,3502.98 1588,3512 1588,3906 1572,3922 813,3922 629,3738 618.77,3727.77 540.23,3727.77 331.77,3727.77 295,3691 295,3639 295,3554 276.06,3535.06 261,3520 156,3520 139.93,3520 112.15,3492.21 112.15,3280.15 78.8,3246.8 78.8,2747.77 240.83,2585.74 240.83,2484.76 265.81,2459.79
VCC_SENSE on BOTTOM "Bottom Layer-VCC_SENSE" (solid, remove dead copper, pour order 56): 1365.79,3036.79 1365.79,2830.79 1411.79,2784.79 1615.79,2784.79 1757.79,2642.79 2006.79,2642.79 2035.79,2671.79 2035.79,3412.79 1991.58,3457 1459.57,3457 1389.79,3526.79 1389.79,3633.79 1347.79,3675.79 987.79,3675.79 944.79,3632.79 936.79,3624.79 936.79,3422.79 1048.79,3310.79 1338.79,3310.79 1376.79,3272.79 1448.79,3200.79 1448.79,3117.79 1365.79,3034.79
GND on PWR "Bottom Layer-GND" (solid, remove dead copper, pour order 52): -89.21,2452.79 275.79,2452.79 283.79,2444.79 283.79,2370.79 211.79,2298.79 207,2294 207,1815.57 257.79,1764.79 746.79,1764.79 790.79,1720.79 790.79,1629.79 751.79,1590.79 717.79,1556.79 717.79,1304.79 717.79,1141.79 646.79,1070.79 646.79,988.79 678.79,956.79 837.79,956.79 876.79,995.79 876.79,1402.79 889.79,1415.79 1158.79,1415.79 1169.79,1404.79 1169.79,1128.79 1146.79,1105.79 1033.79,1105.79 990.79,1062.79 990.79,956.79 990.79,952.95 1008.75,934.99 1008.75,780.75 857.79,629.79 807.79,629.79 719.79,629.79 -44.21,629.79 -79.21,664.79 -93.21,678.79 -93.21,2429.79 -93.21,2448.79
GND on PWR "Bottom Layer-GND" (solid, remove dead copper, pour order 53): -30.21,-91.21 2145.79,-91.21 2189.79,-47.21 2192.79,-44.21 2192.79,8.79 2192.79,1859.79 1625.79,1859.79 1597.79,1831.79 1597.79,1120.79 1566.79,1089.79 1558.79,1081.79 1558.79,820.79 1517.79,779.79 967.79,779.79 839.79,651.79 -75.21,651.79 -96.21,630.79 -96.21,-35.21 -56.21,-75.21 -40.21,-91.21
VDD_PA on PWR "Bottom Layer-VDD_PA" (solid, remove dead copper, pour order 49): 1225.79,941.79 1261.79,905.79 1398.79,905.79 1572.79,905.79 1637.79,970.79 1637.79,1436.78 1603.79,1470.79 1522.79,1470.79 1512.79,1460.79 1479.79,1427.79 1479.79,1008.79 1458.79,987.79 1384.79,987.79 1305.79,1066.79 1262.79,1066.79 1219.79,1023.79 1219.79,947.79
VDD_ANA on PWR "Bottom Layer-VDD_ANA" (solid, remove dead copper, pour order 48): 1033.01,934.98 1201.99,934.99 1208.79,941.79 1211.79,944.79 1211.79,1016.79 1211.79,1030.79 1249.79,1068.79 1261.79,1080.79 1306.79,1080.79 1308.79,1080.79 1386.79,1002.79 1454.79,1002.79 1470.79,1018.79 1470.79,1096.79 1429.79,1137.79 1266.51,1137.79 1252.79,1151.51 1252.79,1476.79 1234.08,1495.49 1198.12,1495.49 1185.79,1483.16 1185.79,1122.79 1143.74,1080.74 1024.45,1080.45 996.08,1052.08 996.08,971.92
VCC_LDO_3V3 on PWR "Bottom Layer-VCC_LDO_3V3" (solid, remove dead copper, pour order 54): 370.79,2466.79 553.79,2466.79 601.79,2514.79 717.79,2630.79 1110.79,2630.79 1129.79,2649.79 1150,2670 1966.7,2670 2010.79,2714.09 2010.79,3890.79 1980.57,3921 -13,3921 -62.21,3871.79 -62.21,2512.61 -16.39,2466.79 369.79,2466.79
VCC_BRD on PWR "Bottom Layer-VCC_BRD" (solid, remove dead copper, pour order 50): 1722.79,1879.79 2156.79,1879.79 2160.79,1883.79 2160.79,2564.81 2104.7,2620.9 1682.9,2620.9 1633.79,2571.79 1609.79,2547.79 1609.79,2207.79 1609.79,1931.79 1657.79,1883.79 1661.79,1879.79 1721.79,1879.79
VBAT_CC on PWR "Bottom Layer-VBAT_CC" (solid, remove dead copper, pour order 51): 672.79,1039.79 672.79,986.79 685.79,973.79 831.79,973.79 861.79,1003.79 861.79,1408.79 878.79,1425.79 1159.79,1425.79 1169.79,1435.79 1169.79,1487.79 1194.7,1512.7 1242.87,1512.7 1263.79,1491.79 1263.79,1151.79 1267.79,1147.79 1457.79,1147.79 1468.79,1158.79 1468.79,1438.79 1547.79,1517.79 1555.79,1525.79 1555.79,1632.79 1555.79,2625.79 1516.79,2664.79 1158.59,2664.79 1117.59,2623.79 792.79,2623.79 788.79,2623.79 624.79,2459.79 620.79,2455.79 607.79,2455.79 164.79,2455.79 138.79,2429.79 138.79,1860.79 218.79,1780.79 400.79,1780.79 909.79,2289.79 947.79,2289.79 961.79,2275.79 985.79,2251.79 985.79,2025.79 770.79,1810.79 770.79,1788.79 789.79,1769.79 867.79,1769.79 896.79,1740.79 985.79,1651.79 985.79,1603.79 985.79,1595.79 964.79,1574.79 827.79,1574.79 735.79,1482.79 730.79,1477.79 730.79,1425.79 730.79,1124.79 680.79,1074.79 672.79,1066.79
no net on M4 3D STEP Bottom "M4 3D STEP Bottom-No Net" (solid, pour order 59): 2155.79,180.79 ccw(c2095.79,180.79) 2095.79,240.79 ccw(c2095.79,180.79) 2035.79,180.79 ccw(c2095.79,180.79) 2095.79,120.79 ccw(c2095.79,180.79) 2155.79,180.79
no net on M4 3D STEP Bottom "M4 3D STEP Bottom-No Net" (solid, pour order 60): 60.79,145.79 ccw(c0.79,145.79) 0.79,205.79 ccw(c0.79,145.79) -59.21,145.79 ccw(c0.79,145.79) 0.79,85.79 ccw(c0.79,145.79) 60.79,145.79
no net on M4 3D STEP Bottom "M4 3D STEP Bottom-No Net" (solid, pour order 58): 2015.79,3505.79 ccw(c1955.79,3505.79) 1955.79,3565.79 ccw(c1955.79,3505.79) 1895.79,3505.79 ccw(c1955.79,3505.79) 1955.79,3445.79 ccw(c1955.79,3505.79) 2015.79,3505.79
GND on GND "Top Layer-GND" (solid, remove dead copper, pour order 47): -38.21,3958.79 2139.79,3958.79 2185.79,3912.79 2185.79,3745.79 2185.79,-9.21 2160.79,-34.21 2115.79,-79.21 2075.79,-79.21 45.79,-79.21 -64.21,30.79 -79.21,45.79 -79.21,194.46 -79.21,3917.79

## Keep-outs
BOTTOM:
  circle w0: c1545.79,1319.79 r16
  circle w0: c1352.79,1462.79 r16
  circle w0: c1570.79,1355.79 r16
Keep-Out Layer:
  circle w1: c976.58,3770.87 r40
  circle w1: c700.99,3770.87 r40
  circle w1: c2014.37,1797.99 r40
  circle w1: c2014.37,2073.58 r40
  circle w1: c87.2,2073.58 r40
  circle w1: c15.79,3611.79 r32
  circle w1: c55.79,3311.79 r32
  circle w1: c-24.21,3311.79 r32
  circle w1: c2111.84,2326.79 r32
  circle w1: c1993.73,2326.79 r32
  circle w1: c0,3849.57 r70
  circle w1: c0.79,145.79 r60
  circle w1: c0,0 r70
  circle w1: c2095.79,180.79 r60
  circle w1: c2101.57,0 r70
  circle w1: c2101.57,3849.57 r70
  circle w1: c415.79,1754.79 r32
  circle w1: c415.79,1834.79 r32
  circle w1: c715.79,1794.79 r32
  circle w1: c1956.1,3858.79 r70
  circle w1: c87.2,1797.99 r40
  lines w1: -19.21,-82.21 cw(c-19.21,-19.21) -82.21,-19.21 -82.21,1797.6 ccw(c-302.14,1936.29) -82.21,2074.97 -82.21,3878.79 cw(c-19.21,3878.79) -19.21,3941.79 2120.79,3941.79 cw(c2119.29,3877.29) 2183.79,3875.79 2183.79,2390.8 2146.79,2390.79 2146.79,2262.79 2183.79,2262.79 2183.79,2074.06 ; 2120.79,-82.21 ccw(c2120.79,-19.21) 2183.79,-19.21 2183.79,1796.79 cw(c2403.71,1935.47) 2183.73,2074.06

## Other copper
TOP:
  rectangle net GND: 872.79,1112.79 1168.06,1408.06
  rectangle net NetC3_1: 296.79,2745.79 357.79,2811.79
  rectangle net GND: 868,3338 896.5,3347.7
  pour cut-out: 39.3,-73.7 2161.3,-73.7 2162.1,-74.5 2160.7,-74.5 2143.3,-91.9 -20.8,-91.9 -23.3,-89.4 -23.3,-87.2 -9,-72.9 -8.2,-73.7 39.24,-73.7
  pour cut-out: 2173.7,2094.5 2104.2,2025 2104.2,1823.6 2181.9,1745.9 2181.9,1805.9 2182.8,1806.8 2149,1840.6 2149,2010.3 2174,2035.3 2174,2093.8
  pour cut-out: -75.6,1785.9 -21,1840.5 -21,2051.2 -79,2109.2 -81.8,2109.2 -91.1,2099.9 -91.1,2066.3 -64.8,2040 -64.8,1909.1 -49,1893.3 -82.21,1860.09 -82.21,1795.18 -73.7,1786.67
  pour cut-out: 1056.43,764.79 733.79,764.79 730.79,767.79 730.79,1050.79 724.79,1056.79 460.79,1056.79 453.79,1063.79 453.79,1356.79 458.79,1361.79 648.79,1361.79 650.79,1363.79 650.79,1493.79 656.79,1499.79 996.79,1499.79 1021.79,1474.79 1021.79,1066.79 1045.79,1042.79 1045.79,917.79 1056.79,906.79 1056.79,765.14
  pour cut-out: 2114.79,1433.79 2114.79,1389.79 1993.79,1389.79 1987.79,1395.79 1987.79,1429.79 1991.79,1433.79
  pour cut-out: 1924.79,57.79 1924.79,33.79 1846.79,33.79 1844.79,35.79 1844.79,53.79 1848.79,57.79
  pour cut-out: 1811.79,57.79 1811.79,33.79 1733.79,33.79 1731.79,35.79 1731.79,53.79 1735.79,57.79
  pour cut-out: 1664.79,56.79 1664.79,32.79 1586.79,32.79 1584.79,34.79 1584.79,52.79 1588.79,56.79
  pour cut-out: 272.98,1938.98 309.79,1938.98 309.79,2005.72 300.03,2015.48 294.16,2015.48 294.16,1960.16
  pour cut-out: 1123.79,480.79 1123.94,480.63 1123.94,431.06 1128.67,435.79 1168.91,435.79 1171.03,433.66 1173.63,431.06 1173.63,470.94 1163.79,480.79
  pour cut-out: 1178.79,-39.21 1116.79,-39.21 1116.79,99.79 1120.79,99.79 1120.79,192.79 1176.79,192.79 1176.79,99.79 1178.79,99.79 1178.79,-39.21
  pour cut-out: 207,1477.79 207.44,1477.77 207.87,1477.71 208.3,1477.62 208.71,1477.49 209.12,1477.32 209.5,1477.12 209.87,1476.88 210.22,1476.62 210.54,1476.32 210.83,1476 211.1,1475.66 211.33,1475.29 211.53,1474.9 211.7,1474.5 211.83,1474.08 211.93,1473.66 211.98,1473.22 212,1472.79 211.98,1472.35 211.93,1471.92 211.83,1471.49 211.7,1471.08 211.53,1470.67 211.47,1470.54 209.9,1467.04 208.64,1463.41 207.7,1459.69 207.09,1455.9 206.81,1452.08 206.86,1448.24 207.25,1444.42 207.97,1440.65 209.02,1436.96 210.38,1433.37 210.6,1432.86 210.92,1432.05 211.17,1431.21 211.35,1430.36 211.45,1429.49 211.47,1428.62 211.42,1427.75 211.29,1426.89 211.09,1426.04 210.81,1425.21 210.46,1424.41 210.05,1423.64 209.57,1422.92 209.02,1422.23 208.42,1421.6 207.77,1421.02 207.07,1420.5 206.33,1420.04 205.55,1419.66 204.73,1419.33 203.9,1419.09 203.04,1418.91 202.18,1418.81 201.47,1418.79 200.1,1418.79 199.23,1418.83 198.37,1418.94 197.51,1419.13 196.68,1419.39 195.88,1419.72 195.1,1420.13 194.37,1420.6 193.68,1421.13 193.03,1421.72 192.44,1422.36 191.91,1423.05 191.44,1423.79 191.04,1424.56 190.71,1425.37 190.44,1426.2 190.25,1427.05 190.14,1427.92 190.1,1428.79 190.14,1429.66 190.25,1430.52 190.44,1431.38 190.71,1432.21 190.97,1432.86 192.38,1436.43 193.47,1440.11 194.24,1443.87 194.68,1447.69 194.78,1451.52 194.55,1455.35 193.99,1459.15 193.09,1462.88 192.55,1464.64 192.31,1465.48 192.15,1466.34 192.06,1467.2 192.05,1468.08 192.11,1468.95 192.25,1469.81 192.46,1470.65 192.75,1471.48 193.1,1472.27 193.53,1473.03 194.02,1473.76 194.57,1474.43 195.18,1475.06 195.84,1475.63 196.54,1476.14 197.29,1476.59 198.08,1476.97 198.89,1477.28 199.73,1477.52 200.59,1477.68 201.46,1477.77 202.04,1477.79 207,1477.79
  pour cut-out: 1673.19,1372.79 1674.06,1372.75 1674.93,1372.64 1675.78,1372.45 1676.61,1372.18 1677.42,1371.85 1678.19,1371.45 1678.92,1370.98 1679.62,1370.45 1680.26,1369.86 1680.85,1369.22 1681.38,1368.52 1681.85,1367.79 1682.25,1367.01 1682.59,1366.21 1682.85,1365.38 1683.04,1364.52 1683.15,1363.66 1683.19,1362.79 1683.15,1361.92 1683.04,1361.05 1682.85,1360.2 1682.59,1359.37 1682.25,1358.56 1681.85,1357.79 1681.38,1357.05 1680.85,1356.36 1680.26,1355.72 1670.86,1346.31 1670.22,1345.73 1669.52,1345.19 1668.79,1344.73 1668.01,1344.32 1667.21,1343.99 1666.38,1343.73 1665.52,1343.54 1664.66,1343.42 1663.79,1343.39 1662.92,1343.42 1662.05,1343.54 1661.2,1343.73 1660.37,1343.99 1659.56,1344.32 1658.79,1344.73 1658.05,1345.19 1657.36,1345.73 1656.72,1346.31 1656.13,1346.96 1655.6,1347.65 1655.13,1348.39 1654.72,1349.16 1654.39,1349.97 1654.13,1350.8 1653.94,1351.65 1653.83,1352.51 1653.79,1353.39 1653.79,1372.79 1673.19,1372.79
  pour cut-out: 1907,1377.79 1907.44,1377.77 1907.87,1377.71 1908.3,1377.62 1908.71,1377.49 1909.12,1377.32 1909.5,1377.12 1909.87,1376.88 1910.22,1376.62 1910.54,1376.32 1910.83,1376 1911.1,1375.66 1911.33,1375.29 1911.53,1374.9 1911.7,1374.5 1911.83,1374.08 1911.93,1373.66 1911.98,1373.22 1912,1372.79 1911.98,1372.35 1911.93,1371.92 1911.83,1371.49 1911.7,1371.08 1911.53,1370.67 1911.47,1370.54 1909.9,1367.04 1908.64,1363.41 1907.7,1359.69 1907.09,1355.9 1906.81,1352.08 1906.86,1348.24 1907.25,1344.42 1907.97,1340.65 1909.02,1336.96 1910.38,1333.37 1910.6,1332.86 1910.92,1332.05 1911.17,1331.21 1911.35,1330.36 1911.45,1329.49 1911.47,1328.62 1911.42,1327.75 1911.29,1326.89 1911.09,1326.04 1910.81,1325.21 1910.46,1324.41 1910.05,1323.64 1909.57,1322.92 1909.02,1322.23 1908.42,1321.6 1907.77,1321.02 1907.07,1320.5 1906.33,1320.04 1905.55,1319.66 1904.73,1319.33 1903.9,1319.09 1903.04,1318.91 1902.18,1318.81 1901.47,1318.79 1900.1,1318.79 1899.23,1318.83 1898.37,1318.94 1897.51,1319.13 1896.68,1319.39 1895.88,1319.72 1895.1,1320.13 1894.37,1320.6 1893.68,1321.13 1893.03,1321.72 1892.44,1322.36 1891.91,1323.05 1891.44,1323.79 1891.04,1324.56 1890.71,1325.37 1890.44,1326.2 1890.25,1327.05 1890.14,1327.92 1890.1,1328.79 1890.14,1329.66 1890.25,1330.52 1890.44,1331.38 1890.71,1332.21 1890.97,1332.86 1892.38,1336.43 1893.47,1340.11 1894.24,1343.87 1894.68,1347.69 1894.78,1351.52 1894.55,1355.35 1893.99,1359.15 1893.09,1362.88 1892.55,1364.64 1892.31,1365.48 1892.15,1366.34 1892.06,1367.2 1892.05,1368.08 1892.11,1368.95 1892.25,1369.81 1892.46,1370.65 1892.75,1371.48 1893.1,1372.27 1893.53,1373.03 1894.02,1373.76 1894.57,1374.43 1895.18,1375.06 1895.84,1375.63 1896.54,1376.14 1897.29,1376.59 1898.08,1376.97 1898.89,1377.28 1899.73,1377.52 1900.59,1377.68 1901.46,1377.77 1902.04,1377.79 1907,1377.79
  pour cut-out: 190.97,1332.86 192.38,1336.43 193.47,1340.11 194.24,1343.87 194.68,1347.69 194.78,1351.52 194.55,1355.35 193.99,1359.15 193.09,1362.88 191.88,1366.53 190.97,1368.71 190.65,1369.52 190.4,1370.36 190.23,1371.22 190.13,1372.08 190.1,1372.95 190.16,1373.83 190.29,1374.69 190.49,1375.54 190.76,1376.36 191.11,1377.16 191.53,1377.93 192.01,1378.66 192.55,1379.34 193.15,1379.98 193.8,1380.55 194.51,1381.07 195.25,1381.53 196.03,1381.92 196.84,1382.24 197.68,1382.49 198.53,1382.66 199.4,1382.76 200.1,1382.79 201.47,1382.79 202.34,1382.75 203.21,1382.64 204.06,1382.45 204.89,1382.18 205.7,1381.85 206.47,1381.45 207.21,1380.98 207.9,1380.45 208.54,1379.86 209.13,1379.22 209.66,1378.52 210.13,1377.79 210.53,1377.01 210.87,1376.21 211.13,1375.38 211.32,1374.52 211.43,1373.66 211.47,1372.79 211.43,1371.92 211.32,1371.05 211.13,1370.2 210.87,1369.37 210.6,1368.71 209.19,1365.14 208.1,1361.46 207.33,1357.7 206.9,1353.89 206.79,1350.05 207.02,1346.22 207.59,1342.42 208.48,1338.69 209.7,1335.05 210.6,1332.86 210.92,1332.05 211.17,1331.21 211.35,1330.36 211.45,1329.49 211.47,1328.62 211.42,1327.75 211.29,1326.89 211.09,1326.04 210.81,1325.21 210.46,1324.41 210.05,1323.64 209.57,1322.92 209.02,1322.23 208.42,1321.6 207.77,1321.02 207.07,1320.5 206.33,1320.04 205.55,1319.66 204.73,1319.33 203.9,1319.09 203.04,1318.91 202.18,1318.81 201.47,1318.79 200.1,1318.79 199.23,1318.83 198.37,1318.94 197.51,1319.13 196.68,1319.39 195.88,1319.72 195.1,1320.13 194.37,1320.6 193.68,1321.13 193.03,1321.72 192.44,1322.36 191.91,1323.05 191.44,1323.79 191.04,1324.56 190.71,1325.37 190.44,1326.2 190.25,1327.05 190.14,1327.92 190.1,1328.79 190.14,1329.66 190.25,1330.52 190.44,1331.38 190.71,1332.21 190.97,1332.86
  pour cut-out: 1816.93,1322.38 1793.33,1298.79 1785.91,1298.79 1785.91,1332.79 1810.64,1332.79 1812.36,1329.36 1814.37,1326.09 1814.56,1325.81 1816.93,1322.38
  pour cut-out: 1982.29,1281.83 2003.24,1302.79 2015.67,1302.79 2015.67,1268.79 1990.94,1268.79 1989.22,1272.22 1987.2,1275.49 1985.1,1278.34 1982.29,1281.83
  pour cut-out: 2118.24,1218.79 2105.91,1218.79 2105.91,1227.79 2105.92,1228.22 2105.98,1228.66 2106.08,1229.08 2106.21,1229.5 2106.37,1229.9 2106.58,1230.29 2106.81,1230.66 2107.08,1231 2107.37,1231.32 2107.69,1231.62 2108.04,1231.88 2108.41,1232.12 2108.79,1232.32 2109.2,1232.49 2109.61,1232.62 2110.04,1232.71 2110.47,1232.77 2110.88,1232.79 2112.45,1232.86 2114,1233.08 2115.54,1233.42 2117.03,1233.9 2118.48,1234.51 2119.87,1235.25 2121.19,1236.1 2122.43,1237.06 2123.58,1238.12 2124.64,1239.29 2125.59,1240.54 2126.42,1241.87 2127.14,1243.26 2127.73,1244.72 2128.2,1246.22 2128.53,1247.75 2128.73,1249.31 2128.79,1250.79 2128.79,1271.95 2131.62,1273.31 2133.54,1274.34 2135.36,1275.53 2137.07,1276.88 2137.45,1277.22 2145.79,1273.49 2145.79,1215.39 2145.75,1214.51 2145.64,1213.65 2145.45,1212.8 2145.18,1211.97 2144.85,1211.16 2144.45,1210.39 2143.98,1209.65 2143.45,1208.96 2142.86,1208.31 2142.22,1207.73 2141.52,1207.19 2140.79,1206.73 2140.01,1206.32 2139.21,1205.99 2138.38,1205.73 2137.52,1205.54 2136.66,1205.42 2135.79,1205.39 2134.92,1205.42 2134.05,1205.54 2133.2,1205.73 2132.37,1205.99 2131.56,1206.32 2130.79,1206.73 2130.05,1207.19 2129.36,1207.73 2128.72,1208.31 2118.24,1218.79
  pour cut-out: 442.99,1095.67 442.99,1101.72 458.79,1101.72 458.79,1073.79 445.79,1073.79 444.22,1073.72 442.66,1073.51 441.13,1073.17 439.63,1072.7 438.18,1072.1 436.79,1071.38 435.46,1070.53 434.22,1069.58 433.06,1068.52 432.93,1068.39 432.29,1067.79 431.61,1067.25 430.88,1066.78 430.11,1066.36 429.3,1066.02 428.47,1065.75 427.62,1065.55 426.76,1065.43 425.89,1065.39 425.02,1065.41 424.15,1065.52 423.3,1065.7 422.46,1065.95 421.65,1066.28 420.88,1066.67 420.14,1067.14 419.44,1067.66 418.79,1068.24 418.72,1068.31 408.43,1078.6 407.84,1079.24 407.31,1079.93 406.84,1080.67 406.44,1081.44 406.11,1082.25 405.84,1083.08 405.66,1083.93 405.54,1084.8 405.5,1085.67 405.54,1086.54 405.66,1087.41 405.84,1088.26 406.11,1089.09 406.44,1089.9 406.84,1090.67 407.31,1091.4 407.84,1092.1 408.43,1092.74 409.08,1093.33 409.77,1093.86 410.5,1094.33 411.28,1094.73 412.08,1095.07 412.92,1095.33 413.77,1095.52 414.63,1095.63 415.5,1095.67 442.99,1095.67
  pour cut-out: 410.89,1025.22 411.48,1024.58 412.01,1023.89 412.48,1023.15 412.89,1022.38 413.22,1021.57 413.48,1020.74 413.67,1019.89 413.79,1019.02 413.82,1018.15 413.78,1017.28 413.67,1016.42 413.48,1015.57 413.22,1014.73 412.89,1013.93 412.48,1013.15 412.01,1012.42 411.67,1011.95 410.75,1010.68 410.16,1009.73 409.7,1008.99 409.17,1008.29 408.58,1007.65 407.94,1007.06 407.25,1006.52 406.52,1006.05 405.75,1005.64 404.94,1005.31 404.11,1005.04 403.26,1004.85 402.39,1004.73 401.52,1004.69 400.65,1004.72 399.79,1004.84 398.93,1005.02 398.1,1005.28 397.29,1005.61 396.52,1006.01 395.78,1006.48 395.09,1007 394.44,1007.59 394.41,1007.62 366.99,1035.05 367.86,1037.92 368.83,1041.64 369.3,1044.27 369.47,1045.12 369.71,1045.96 370.02,1046.78 370.41,1047.56 370.85,1048.31 371.37,1049.01 371.94,1049.67 372.57,1050.28 373.25,1050.83 373.97,1051.31 374.73,1051.74 375.53,1052.09 376.35,1052.37 377.2,1052.59 378.06,1052.72 378.93,1052.78 379.81,1052.77 380.67,1052.67 381.53,1052.51 382.37,1052.27 383.18,1051.95 383.97,1051.57 384.71,1051.12 385.42,1050.61 386.08,1050.04 386.26,1049.86 410.89,1025.22
  pour cut-out: 775.79,83.41 739.79,83.41 739.79,124.41 775.79,124.41
  pour cut-out: 831.79,1088.33 832.56,1087.56 1196.73,1087.56 1197.96,1088.79 1197.96,1428.79 831.79,1428.79
  pour cut-out: 1232.79,804.79 1232.79,958.79 1222.79,968.79 1222.79,1028.79 1227.79,1033.79 1264.79,1033.79 1289.88,1008.69 1436.69,1008.69 1453.79,1025.79 1453.79,1118.79 1448.79,1123.79 1387.29,1123.79 1375.48,1111.98 1333.22,1111.98 1321.41,1123.79 1321.41,1328.17 1179.79,1469.79 1042.79,1469.79 942.79,1569.79 942.79,1765.79 947.79,1770.79 1612.79,1770.79 1612.79,804.79
  pour cut-out: 367.15,1993.48 368.04,1992.6 545.42,1992.6 545.42,2205.16 544.79,2205.79 369.79,2205.79 364.79,2200.79 365.88,2199.69 365.88,1994.98
  pour cut-out: 1647.48,442.39 1647.48,418.39 1569.48,418.39 1567.48,420.39 1567.48,438.39 1571.48,442.39
  pour cut-out: 1229.6,-94.91 1315.79,-94.91 1315.79,-43.41 1335.59,-43.41 1335.59,101.94 1099.37,101.94 1099.37,-43.41 1229.6,-43.41
  pour cut-out: 650.79,1493.79 650.79,1666.36 663,1678.57 712.43,1678.57 737,1654 737,1580
  pour cut-out: 2035,1754 2056,1754 2057,1755 2057,1771.38 2055.74,1772.65 2053.39,1772.65 2034.68,1753.94
  pour cut-out: 1296,1769 1303,1762 1566,1762 1575.79,1771.79 1575.79,1869.79 1538.79,1906.79 1335.79,1906.79 1296,1867
  text ".layer_Name" at -459.21,-1173.21 h60
GND:
  pour cut-out: 39.3,-73.7 2161.3,-73.7 2162.1,-74.5 2160.7,-74.5 2143.3,-91.9 -20.8,-91.9 -23.3,-89.4 -23.3,-87.2 -9,-72.9 -8.2,-73.7 39.24,-73.7
  pour cut-out: 2173.7,2094.5 2104.2,2025 2104.2,1823.6 2181.9,1745.9 2181.9,1805.9 2182.8,1806.8 2149,1840.6 2149,2010.3 2174,2035.3 2174,2093.8
  pour cut-out: -75.6,1785.9 -21,1840.5 -21,2051.2 -79,2109.2 -81.8,2109.2 -91.1,2099.9 -91.1,2066.3 -64.8,2040 -64.8,1909.1 -49,1893.3 -82.21,1860.09 -82.21,1795.18 -73.7,1786.67
  pour cut-out: 1373.18,1462.79 1371.63,1470.59 1367.21,1477.21 1360.59,1481.63 1352.79,1483.18 1344.98,1481.63 1338.37,1477.21 1333.95,1470.59 1332.4,1462.79 1333.95,1454.98 1338.37,1448.37 1344.98,1443.95 1352.79,1442.4 1360.59,1443.95 1367.21,1448.37 1371.63,1454.98 1373.18,1462.79
  pour cut-out: 1381.18,1185.79 1379.63,1193.59 1375.21,1200.21 1368.59,1204.63 1360.79,1206.18 1352.98,1204.63 1346.37,1200.21 1341.95,1193.59 1340.4,1185.79 1341.95,1177.98 1346.37,1171.37 1352.98,1166.95 1360.79,1165.4 1368.59,1166.95 1375.21,1171.37 1379.63,1177.98 1381.18,1185.79
  pour cut-out: 1398.18,1249.79 1396.63,1257.59 1392.21,1264.21 1385.59,1268.63 1377.79,1270.18 1369.98,1268.63 1363.37,1264.21 1358.95,1257.59 1357.4,1249.79 1358.95,1241.98 1363.37,1235.37 1369.98,1230.95 1377.79,1229.4 1385.59,1230.95 1392.21,1235.37 1396.63,1241.98 1398.18,1249.79
  pour cut-out: 1211.18,765.79 1209.63,773.59 1205.21,780.21 1198.59,784.63 1190.79,786.18 1182.98,784.63 1176.37,780.21 1171.95,773.59 1170.4,765.79 1171.95,757.98 1176.37,751.37 1182.98,746.95 1190.79,745.4 1198.59,746.95 1205.21,751.37 1209.63,757.98 1211.18,765.79
  pour cut-out: 1099.37,106.14 1335.59,106.14 1335.59,-90.71 1099.37,-90.71
  text ".layer_Name" at -453.21,-1176.21 h60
